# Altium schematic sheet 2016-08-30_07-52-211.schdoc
size 252 x 172 mm; SheetNumber: 1; SheetTotal: 1
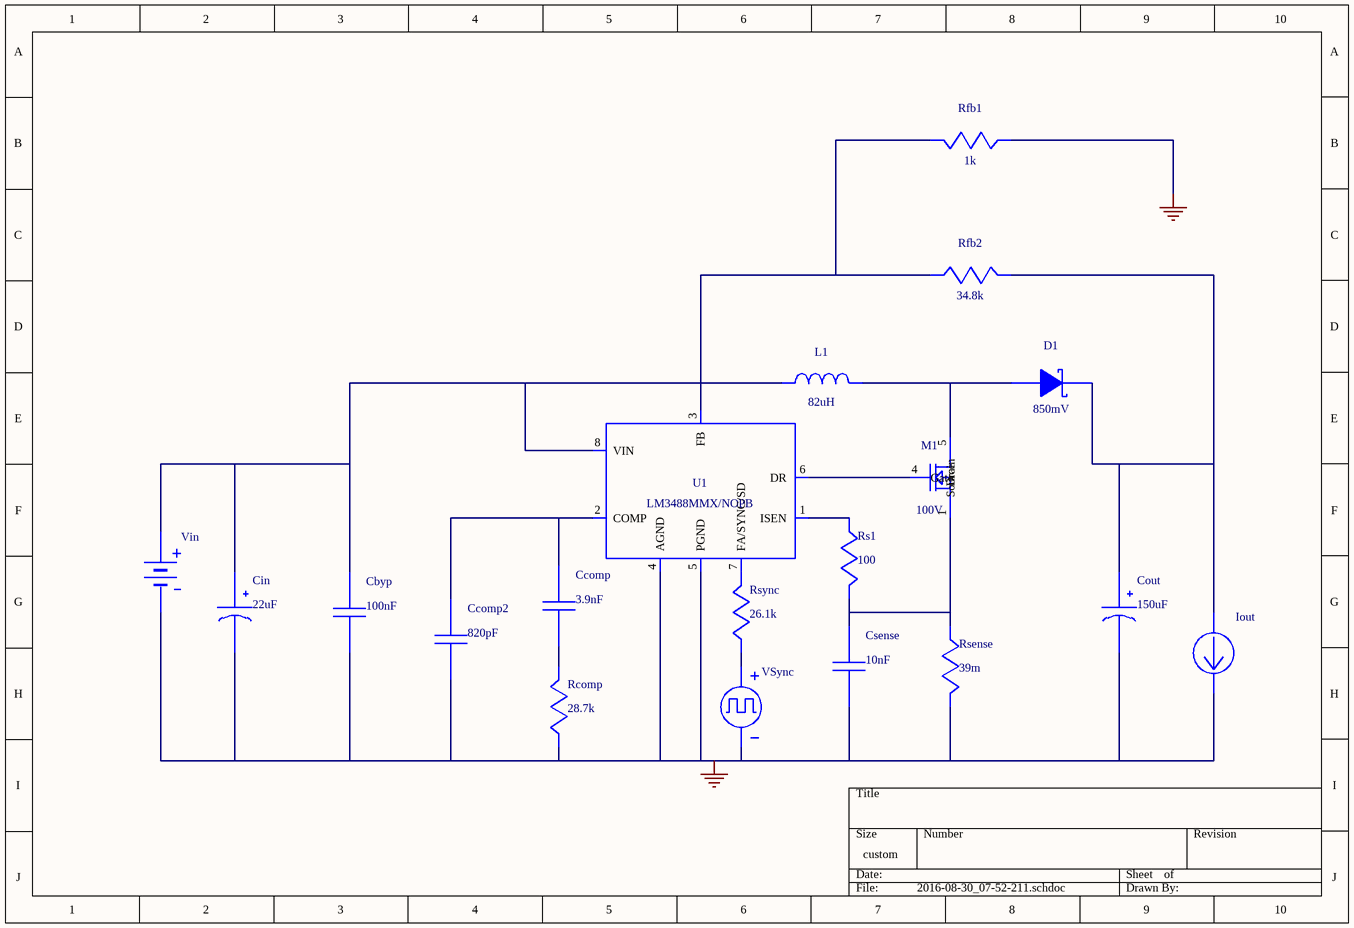
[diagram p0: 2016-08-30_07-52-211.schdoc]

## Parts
Cbyp  value 100nF  (hidden comment: C0805C104K5RACTU)
Ccomp  value 3.9nF  (hidden comment: CC0805KRX7R9BB392)
Ccomp2  value 820pF  (hidden comment: CC0805KRX7R9BB821)
Cin  value 22uF  (hidden comment: UUD1H220MCL1GS)
Cout  value 150uF  (hidden comment: EEV-FK2A151M)
Csense  value 10nF  (hidden comment: GRM216R71H103KA01D)
D1  value 850mV  (hidden comment: DFLS1200-7)
Iout  WB_CURRENT_LOAD  (value not drawn)
L1  value 82uH  (hidden comment: SDR1307-820KL)
M1  value 100V  (hidden comment: CSD19537Q3)
Rcomp  value 28.7k  (hidden comment: CRCW040228K7FKED)
Rfb1  value 1k  (hidden comment: CRCW04021K00FKED)
Rfb2  value 34.8k  (hidden comment: CRCW040234K8FKED)
Rs1  value 100  (hidden comment: CRCW0402100RFKED)
Rsense  value 39m  (hidden comment: ERJ-L14KF39MU)
Rsync  value 26.1k  (hidden comment: CRCW040226K1FKED)
U1  LM3488MM/NOPB  (value not drawn)
Vin  WB_BATTERY  (value not drawn)
VSync  WB_SYNC_SOURCE  (value not drawn)

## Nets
0: Cbyp.2 Ccomp2.2 Cin.2(-) Cout.2(-) Csense.2 Iout.2(-) Rcomp.2 Rfb1.2 Rsense.1 U1.4(AGND) U1.5(PGND) Vin.2(-) VSync.2(-)
NetCbyp_1: Cbyp.1 Cin.1(+) L1.1 U1.8(VIN) Vin.1(+)
NetCcomp_1: Ccomp.1 Ccomp2.1 U1.2(COMP)
NetCcomp_2: Ccomp.2 Rcomp.1
NetCout_1: Cout.1(+) D1.1(K) Iout.1(+) Rfb2.1
NetCsense_1: Csense.1 M1.1(Source) M1.2(Source) M1.3(Source) Rs1.1 Rsense.2
NetD1_2: D1.2(A) L1.2 M1.5(Drain) M1.6(Drain) M1.7(Drain) M1.8(Drain) M1.9(Drain)
NetM1_4: M1.4(Gate) U1.6(DR)
NetRfb1_1: Rfb1.1 Rfb2.2 U1.3(FB)
NetRs1_2: Rs1.2 U1.1(ISEN)
NetRsync_1: Rsync.1 U1.7(FA/SYNC/SD)
NetRsync_2: Rsync.2 VSync.1(+)

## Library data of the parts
Cbyp = C0805C104K5RACTU: Manufacturer Name: Kemet
Ccomp = CC0805KRX7R9BB392: CC0805KRX7R9BB39; Manufacturer Name: Yageo America
Ccomp2 = CC0805KRX7R9BB821: CC0805KRX7R9BB82; Manufacturer Name: Yageo America
Cin = UUD1H220MCL1GS: Manufacturer Name: Nichicon
Cout = EEV-FK2A151M: Manufacturer Name: Panasonic
Csense = GRM216R71H103KA01D: GRM216R71H103KA0; Manufacturer Name: MuRata
D1 = DFLS1200-7: Manufacturer Name: Diodes Inc.
L1 = SDR1307-820KL: Manufacturer Name: Bourns
M1 = CSD19537Q3: Manufacturer Name: Texas Instruments
Rcomp = CRCW040228K7FKED: Manufacturer Name: Vishay-Dale
Rfb1 = CRCW04021K00FKED: Manufacturer Name: Vishay-Dale
Rfb2 = CRCW040234K8FKED: Manufacturer Name: Vishay-Dale
Rs1 = CRCW0402100RFKED: Manufacturer Name: Vishay-Dale
Rsense = ERJ-L14KF39MU: Manufacturer Name: Panasonic
Rsync = CRCW040226K1FKED: Manufacturer Name: Vishay-Dale
U1 = LM3488MM/NOPB: LM3488MMX/NOPB; Manufacturer Name: Texas Instruments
